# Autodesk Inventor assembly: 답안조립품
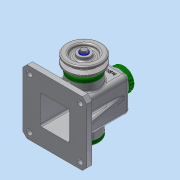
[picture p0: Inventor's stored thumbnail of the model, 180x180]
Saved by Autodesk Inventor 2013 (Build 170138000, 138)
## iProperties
Created: 2018-10
Part Number: 답안조립품
Document SubType Name: Assembly
Designer: Administrator
Author: Administrator
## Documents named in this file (14)
- C:\Users\Administrator\Desktop\인벤터시험\481013V1011\답안조립품.iam
- C:\Users\Administrator\Desktop\인벤터시험\481013V1011\본체.ipt
- C:\Users\Administrator\Desktop\인벤터시험\481013V1011\V-벨트풀리.ipt
- C:\Users\Administrator\Desktop\인벤터시험\481013V1011\뒤커버.ipt
- C:\Users\Administrator\Desktop\인벤터시험\481013V1011\멈춤링 15 x 1.ipt
- C:\Users\Administrator\Desktop\인벤터시험\481013V1011\베어링 15 x 35 x 11.ipt
- C:\Users\Administrator\Desktop\인벤터시험\481013V1011\볼트 M4 x 10.ipt
- C:\Users\Administrator\Desktop\인벤터시험\481013V1011\볼트 M6 x 12.ipt
- C:\Users\Administrator\Desktop\인벤터시험\481013V1011\상부캡.ipt
- C:\Users\Administrator\Desktop\인벤터시험\481013V1011\앞커버.ipt
- C:\Users\Administrator\Desktop\인벤터시험\481013V1011\오일실 15 25 7.ipt
- C:\Users\Administrator\Desktop\인벤터시험\481013V1011\와셔.ipt
- C:\Users\Administrator\Desktop\인벤터시험\481013V1011\축.ipt
- C:\Users\Administrator\Desktop\인벤터시험\481013V1011\키 5 x 5 x 14.ipt
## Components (1 placed, 1 different names)
1. V-벨트풀리:1
